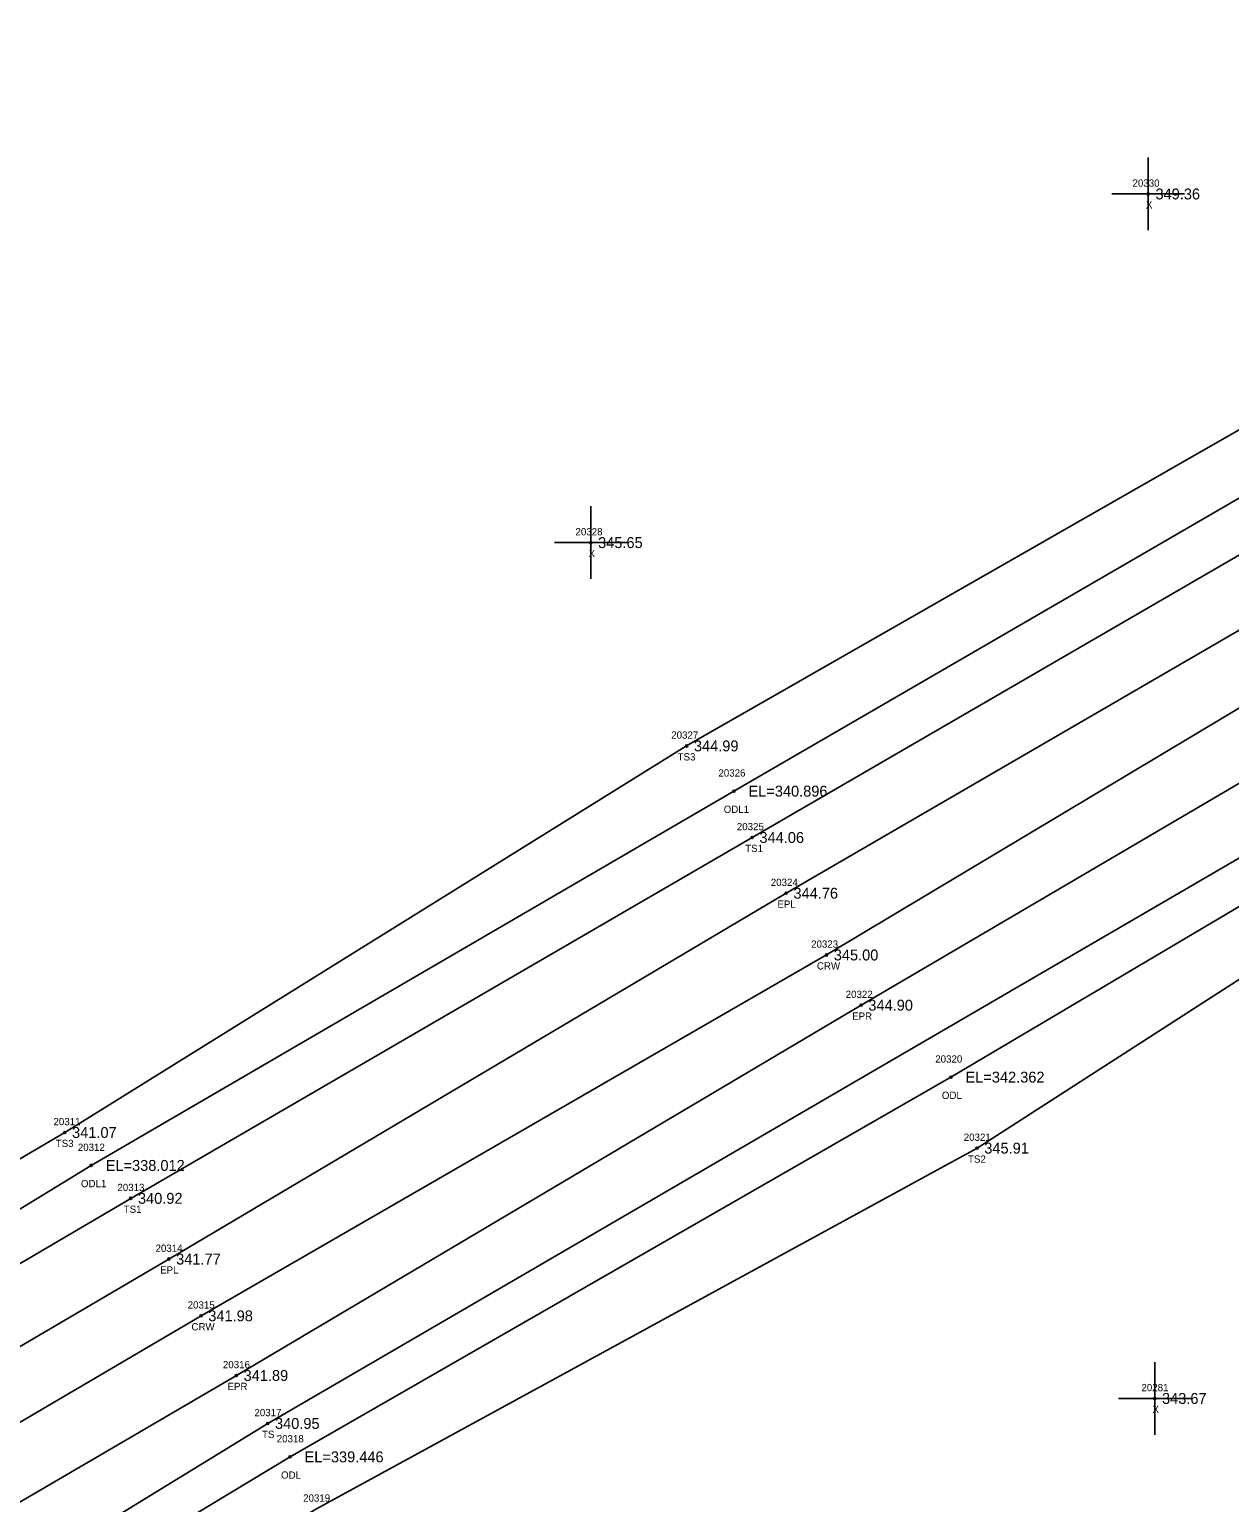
# Model space of a CAD drawing. Extents: x 2231109 to 2232328, y 1035718 to 1036919.
# Drawn here: x 2232002.6 to 2232167.8, y 1036686.7 to 1036889.4 of the extents above; entities that cross this region are included whole.
import ezdxf

# ---------------------------------------------------------------- set-up
doc = ezdxf.new("R2010")
doc.units = 0
for name, color, linetype in [('RD_DTM_BkLn1', 7, 'Continuous'), ('RD_DTM_BkLn2', 7, 'Continuous'), ('RD_DTM_BkLn_txCode', 7, 'Continuous'), ('RD_EX_H2O', 7, 'Continuous'), ('RD_EX_H2O_txCode', 7, 'Continuous'), ('RD_EX_Misc', 7, 'Continuous'), ('RD_EX_Misc_txCode', 7, 'Continuous'), ('RD_EX_Road', 7, 'Continuous'), ('RD_EX_Road_txCode', 7, 'Continuous'), ('RD_EX_TX_H2O_ELEV', 7, 'Continuous'), ('RD_EX_TX_Misc_ELEV', 7, 'Continuous'), ('RD_EX_TX_Road_ELEV', 7, 'Continuous'), ('RD_HC_Survey_ELEV', 7, 'Continuous'), ('RD_HC_Survey_txCode', 7, 'Continuous'), ('RD_SMD_Locator', 7, 'Continuous')]:
    doc.layers.add(name, color=color, linetype=linetype)

msp = doc.modelspace()

# ---------------------------------------------------------------- linework, layer by layer
at = {"layer": 'RD_DTM_BkLn1'}
msp.add_lwpolyline([(2231606.1, 1036462.92), (2231686.87, 1036511.89), (2231772.7, 1036562.84), (2231856.39, 1036612), (2231941.22, 1036662.52), (2232026.21, 1036712.41), (2232112.3, 1036762.07), (2232195.17, 1036811.63), (2232281.68, 1036862.71)], dxfattribs=at)
at = {"layer": 'RD_DTM_BkLn2'}
for points in [[(2231735.08, 1036566.99), (2231733.44, 1036571.38), (2231838.97, 1036638.65), (2231923.32, 1036688.26), (2232007.46, 1036737.64), (2232093.05, 1036790.84), (2232175.73, 1036838.16), (2232263.96, 1036889.44)], [(2231735.08, 1036566.99), (2231739.37, 1036565.02), (2231846.03, 1036627.82), (2231929.8, 1036677.63), (2232016.53, 1036728.58), (2232102.07, 1036778.24), (2232186.07, 1036826.97), (2232269.67, 1036876.59)], [(2231718.4, 1036498.96), (2231713.38, 1036506.48), (2231734.88, 1036516.5), (2231783.19, 1036543.78), (2231867.56, 1036594.75), (2232035.39, 1036697.6), (2232204.37, 1036795.95), (2232291.91, 1036847.83)], [(2231718.4, 1036498.96), (2231722.77, 1036493.83), (2231728.85, 1036494.16), (2231749.87, 1036507.43), (2231788.02, 1036534.9), (2231874.52, 1036587.15), (2231959.93, 1036637.18), (2232042.1, 1036685.84), (2232133.02, 1036735.49), (2232212.03, 1036786.36), (2232298.34, 1036837.91)]]:
    msp.add_lwpolyline(points, dxfattribs=at)
at = {"layer": 'RD_EX_H2O'}
for points in [[(2231741.7, 1036569.83), (2231843.08, 1036632.45), (2231926.34, 1036681.31), (2232011.09, 1036733.11), (2232099.56, 1036784.62), (2232183.31, 1036833.18), (2232266.22, 1036880.93)], [(2231720.77, 1036499.78), (2231736.43, 1036508.96), (2231742.17, 1036508.27), (2231745.29, 1036514.03), (2231785.52, 1036539.9), (2231869.59, 1036591.16), (2232038.46, 1036693), (2232129.43, 1036745.26), (2232207.65, 1036791.56), (2232294.95, 1036842.48)]]:
    msp.add_lwpolyline(points, dxfattribs=at)
at = {"layer": 'RD_EX_Misc'}
for p, q in [((2232156.58, 1036861.8), (2232156.58, 1036871.8)), ((2232151.58, 1036866.8), (2232161.58, 1036866.8)), ((2232079.86, 1036813.82), (2232079.86, 1036823.82)), ((2232074.86, 1036818.82), (2232084.86, 1036818.82)), ((2232157.48, 1036696.04), (2232157.48, 1036706.04)), ((2232152.48, 1036701.04), (2232162.48, 1036701.04))]:
    msp.add_line(p, q, dxfattribs=at)
at = {"layer": 'RD_EX_Road'}
for points in [[(2231606.1, 1036462.92), (2231601.27, 1036470.82), (2231681.58, 1036519.84), (2231764.99, 1036568.78), (2231851.5, 1036619.95), (2231935.62, 1036669.65), (2232021.78, 1036720.22), (2232106.75, 1036770.57), (2232190.54, 1036819.2), (2232275.92, 1036870.27)], [(2231606.1, 1036462.92), (2231610.57, 1036455.36), (2231692.09, 1036503.24), (2231706.07, 1036512.59), (2231777.1, 1036553.27), (2231861.39, 1036604.65), (2231946.39, 1036654.77), (2232031.07, 1036704.2), (2232117.06, 1036755.16), (2232199.91, 1036803.8), (2232286.7, 1036855.36)]]:
    msp.add_lwpolyline(points, dxfattribs=at)
at = {"layer": 'RD_SMD_Locator'}
for centre in [(2232156.58, 1036866.8), (2232079.86, 1036818.82), (2232093.05, 1036790.84), (2232099.56, 1036784.62), (2232102.07, 1036778.24), (2232106.75, 1036770.57), (2232112.3, 1036762.07), (2232117.06, 1036755.16), (2232129.43, 1036745.26), (2232007.46, 1036737.64), (2232133.02, 1036735.49), (2232011.09, 1036733.11), (2232016.53, 1036728.58), (2232021.78, 1036720.22), (2232026.21, 1036712.41), (2232031.07, 1036704.2), (2232157.48, 1036701.04), (2232035.39, 1036697.6), (2232038.46, 1036693)]:
    msp.add_circle(centre, 0.15, dxfattribs=at)

# ---------------------------------------------------------------- texts
at = {"layer": 'RD_DTM_BkLn_txCode'}
for s, p in [('20327', (2232090.93, 1036791.84)), ('TS3', (2232091.81, 1036788.84)), ('20325', (2232099.96, 1036779.24)), ('TS1', (2232101.11, 1036776.24)), ('20311', (2232005.9, 1036738.64)), ('20321', (2232131.19, 1036736.49)), ('TS3', (2232006.21, 1036735.64)), ('TS2', (2232131.78, 1036733.49)), ('20313', (2232014.7, 1036729.58)), ('TS1', (2232015.57, 1036726.58)), ('20317', (2232033.56, 1036698.6)), ('TS', (2232034.6, 1036695.6)), ('20319', (2232040.26, 1036686.84))]:
    msp.add_text(s, height=1, dxfattribs=at).set_placement(p)
at = {"layer": 'RD_EX_H2O_txCode'}
for s, p in [('20326', (2232097.42, 1036786.62)), ('ODL1', (2232098.15, 1036781.62)), ('20320', (2232127.27, 1036747.26)), ('ODL', (2232128.18, 1036742.26)), ('20312', (2232009.25, 1036735.11)), ('ODL1', (2232009.68, 1036730.11)), ('20318', (2232036.63, 1036695)), ('ODL', (2232037.22, 1036690))]:
    msp.add_text(s, height=1, dxfattribs=at).set_placement(p)
at = {"layer": 'RD_EX_Misc_txCode'}
for s, p in [('20330', (2232154.42, 1036867.8)), ('X', (2232156.26, 1036864.8)), ('20328', (2232077.75, 1036819.82)), ('X', (2232079.55, 1036816.82)), ('20281', (2232155.65, 1036702.04)), ('X', (2232157.17, 1036699.04))]:
    msp.add_text(s, height=1, dxfattribs=at).set_placement(p)
at = {"layer": 'RD_EX_Road_txCode'}
for s, p in [('20324', (2232104.63, 1036771.57)), ('EPL', (2232105.54, 1036768.57)), ('20322', (2232114.94, 1036756.16)), ('EPR', (2232115.83, 1036753.16)), ('20314', (2232019.95, 1036721.22)), ('EPL', (2232020.58, 1036718.22)), ('20316', (2232029.22, 1036705.2)), ('EPR', (2232029.85, 1036702.2))]:
    msp.add_text(s, height=1, dxfattribs=at).set_placement(p)
at = {"layer": 'RD_EX_TX_H2O_ELEV'}
for s, p in [('EL=340.896', (2232101.56, 1036783.87)), ('EL=342.362', (2232131.43, 1036744.51)), ('EL=338.012', (2232013.09, 1036732.36)), ('EL=339.446', (2232040.46, 1036692.25))]:
    msp.add_text(s, height=1.5, dxfattribs=at).set_placement(p)
at = {"layer": 'RD_EX_TX_Misc_ELEV'}
for s, p in [('349.36', (2232157.58, 1036866.05)), ('345.65', (2232080.86, 1036818.07)), ('344.99', (2232094.05, 1036790.09)), ('344.06', (2232103.07, 1036777.49)), ('341.07', (2232008.46, 1036736.89)), ('345.91', (2232134.02, 1036734.74)), ('340.92', (2232017.53, 1036727.83)), ('343.67', (2232158.48, 1036700.29)), ('340.95', (2232036.39, 1036696.85))]:
    msp.add_text(s, height=1.5, dxfattribs=at).set_placement(p)
at = {"layer": 'RD_EX_TX_Road_ELEV'}
for s, p in [('344.76', (2232107.75, 1036769.82)), ('344.90', (2232118.06, 1036754.41)), ('341.77', (2232022.78, 1036719.47)), ('341.89', (2232032.07, 1036703.45))]:
    msp.add_text(s, height=1.5, dxfattribs=at).set_placement(p)
at = {"layer": 'RD_HC_Survey_ELEV'}
for s, p in [('345.00', (2232113.3, 1036761.32)), ('341.98', (2232027.21, 1036711.66))]:
    msp.add_text(s, height=1.5, dxfattribs=at).set_placement(p)
at = {"layer": 'RD_HC_Survey_txCode'}
for s, p in [('20323', (2232110.18, 1036763.07)), ('CRW', (2232110.98, 1036760.07)), ('20315', (2232024.37, 1036713.41)), ('CRW', (2232024.89, 1036710.41))]:
    msp.add_text(s, height=1, dxfattribs=at).set_placement(p)

doc.saveas('drawing.dxf')
